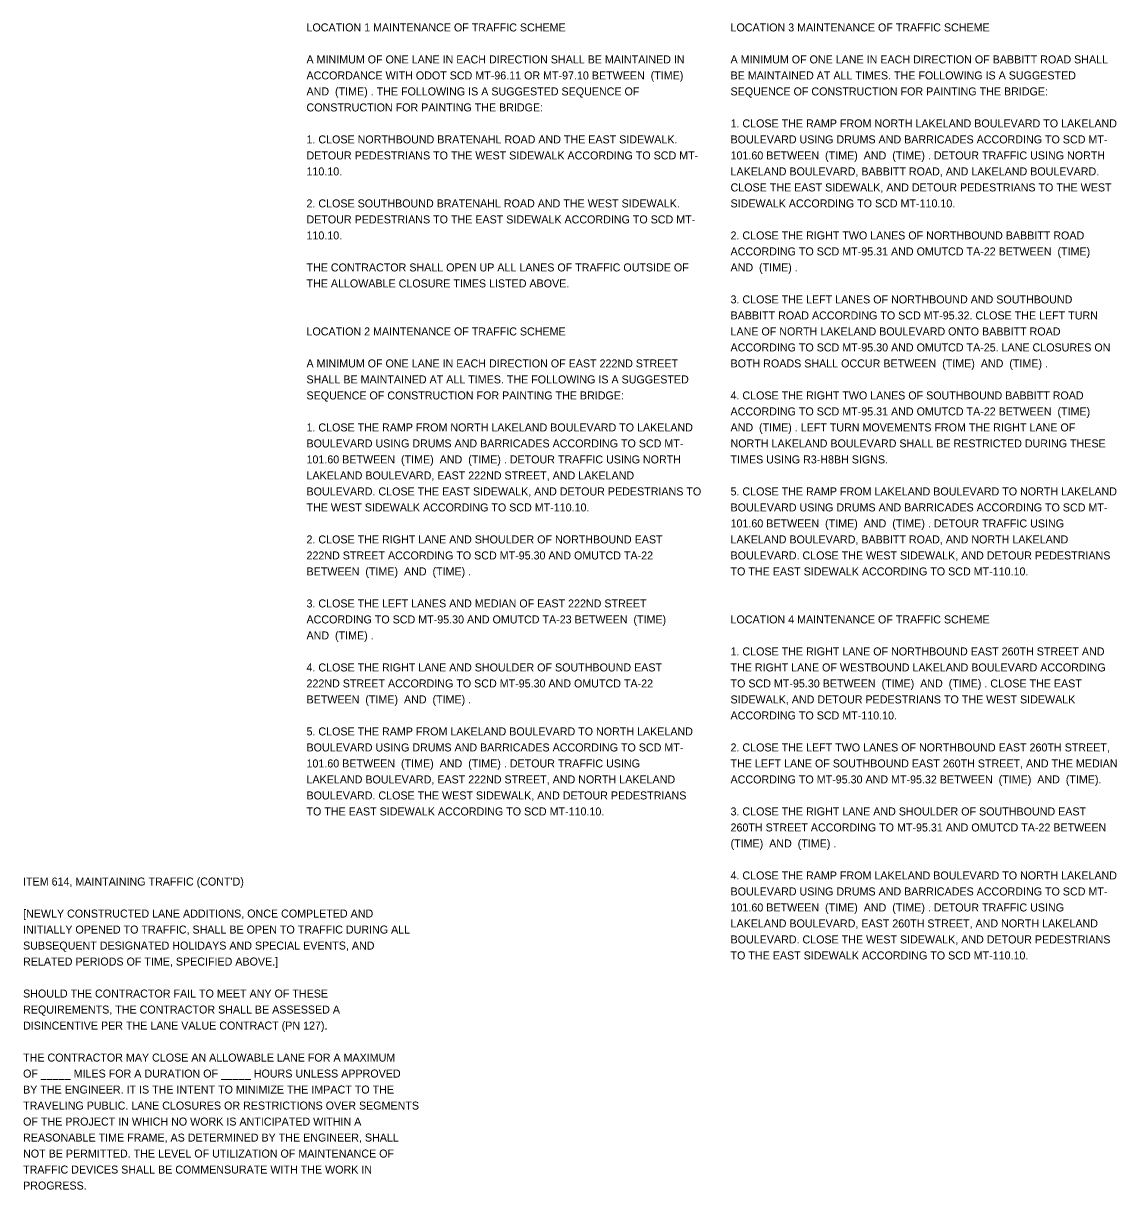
# Model space of a CAD drawing. Extents: x -18.5 to 46, y -14.2 to 42.5.
# Drawn here: x 12.29 to 31.42, y 22.11 to 42.52 of the extents above; entities that cross this region are included whole.
import ezdxf

# ---------------------------------------------------------------- set-up
doc = ezdxf.new("R2010")
doc.units = 0
doc.layers.add('SN_X_Public', color=7, linetype='Continuous')

msp = doc.modelspace()

# ---------------------------------------------------------------- texts
at = {"layer": 'SN_X_Public'}
for s, p in [('LOCATION 1 MAINTENANCE OF TRAFFIC SCHEME ', (17.24, 42.374)), ('LOCATION 3 MAINTENANCE OF TRAFFIC SCHEME ', (24.66, 42.374)), ('A MINIMUM OF ONE LANE IN EACH DIRECTION SHALL BE MAINTAINED IN ', (17.24, 41.814)), ('A MINIMUM OF ONE LANE IN EACH DIRECTION OF BABBITT ROAD SHALL ', (24.66, 41.814)), ('ACCORDANCE WITH ODOT SCD MT-96.11 OR MT-97.10 BETWEEN  (TIME)  ', (17.24, 41.534)), ('BE MAINTAINED AT ALL TIMES. THE FOLLOWING IS A SUGGESTED ', (24.66, 41.534)), ('AND  (TIME) . THE FOLLOWING IS A SUGGESTED SEQUENCE OF ', (17.24, 41.254)), ('SEQUENCE OF CONSTRUCTION FOR PAINTING THE BRIDGE:', (24.66, 41.254)), ('CONSTRUCTION FOR PAINTING THE BRIDGE:', (17.24, 40.974)), ('1. CLOSE THE RAMP FROM NORTH LAKELAND BOULEVARD TO LAKELAND ', (24.66, 40.694)), ('1. CLOSE NORTHBOUND BRATENAHL ROAD AND THE EAST SIDEWALK. ', (17.24, 40.414)), ('BOULEVARD USING DRUMS AND BARRICADES ACCORDING TO SCD MT-', (24.66, 40.414)), ('DETOUR PEDESTRIANS TO THE WEST SIDEWALK ACCORDING TO SCD MT-', (17.24, 40.134)), ('101.60 BETWEEN  (TIME)  AND  (TIME) . DETOUR TRAFFIC USING NORTH ', (24.66, 40.134)), ('110.10.', (17.24, 39.854)), ('LAKELAND BOULEVARD, BABBITT ROAD, AND LAKELAND BOULEVARD. ', (24.66, 39.854)), ('CLOSE THE EAST SIDEWALK, AND DETOUR PEDESTRIANS TO THE WEST ', (24.66, 39.574)), ('2. CLOSE SOUTHBOUND BRATENAHL ROAD AND THE WEST SIDEWALK. ', (17.24, 39.294)), ('SIDEWALK ACCORDING TO SCD MT-110.10.', (24.66, 39.294)), ('DETOUR PEDESTRIANS TO THE EAST SIDEWALK ACCORDING TO SCD MT-', (17.24, 39.014)), ('110.10.', (17.24, 38.734)), ('2. CLOSE THE RIGHT TWO LANES OF NORTHBOUND BABBITT ROAD ', (24.66, 38.734)), ('ACCORDING TO SCD MT-95.31 AND OMUTCD TA-22 BETWEEN  (TIME)  ', (24.66, 38.454)), ('THE CONTRACTOR SHALL OPEN UP ALL LANES OF TRAFFIC OUTSIDE OF ', (17.24, 38.174)), ('AND  (TIME) .', (24.66, 38.174)), ('THE ALLOWABLE CLOSURE TIMES LISTED ABOVE.', (17.24, 37.894)), ('3. CLOSE THE LEFT LANES OF NORTHBOUND AND SOUTHBOUND ', (24.66, 37.614)), ('BABBITT ROAD ACCORDING TO SCD MT-95.32. CLOSE THE LEFT TURN ', (24.66, 37.334)), ('LOCATION 2 MAINTENANCE OF TRAFFIC SCHEME ', (17.24, 37.054)), ('LANE OF NORTH LAKELAND BOULEVARD ONTO BABBITT ROAD ', (24.66, 37.054)), ('ACCORDING TO SCD MT-95.30 AND OMUTCD TA-25. LANE CLOSURES ON ', (24.66, 36.774)), ('A MINIMUM OF ONE LANE IN EACH DIRECTION OF EAST 222ND STREET ', (17.24, 36.494)), ('BOTH ROADS SHALL OCCUR BETWEEN  (TIME)  AND  (TIME) .', (24.66, 36.494)), ('SHALL BE MAINTAINED AT ALL TIMES. THE FOLLOWING IS A SUGGESTED ', (17.24, 36.214)), ('SEQUENCE OF CONSTRUCTION FOR PAINTING THE BRIDGE:', (17.24, 35.934)), ('4. CLOSE THE RIGHT TWO LANES OF SOUTHBOUND BABBITT ROAD ', (24.66, 35.934)), ('ACCORDING TO SCD MT-95.31 AND OMUTCD TA-22 BETWEEN  (TIME)  ', (24.66, 35.654)), ('1. CLOSE THE RAMP FROM NORTH LAKELAND BOULEVARD TO LAKELAND ', (17.24, 35.374)), ('AND  (TIME) . LEFT TURN MOVEMENTS FROM THE RIGHT LANE OF ', (24.66, 35.374)), ('BOULEVARD USING DRUMS AND BARRICADES ACCORDING TO SCD MT-', (17.24, 35.094)), ('NORTH LAKELAND BOULEVARD SHALL BE RESTRICTED DURING THESE ', (24.66, 35.094)), ('101.60 BETWEEN  (TIME)  AND  (TIME) . DETOUR TRAFFIC USING NORTH ', (17.24, 34.814)), ('TIMES USING R3-H8BH SIGNS.', (24.66, 34.814)), ('LAKELAND BOULEVARD, EAST 222ND STREET, AND LAKELAND ', (17.24, 34.534)), ('BOULEVARD. CLOSE THE EAST SIDEWALK, AND DETOUR PEDESTRIANS TO ', (17.24, 34.254)), ('5. CLOSE THE RAMP FROM LAKELAND BOULEVARD TO NORTH LAKELAND ', (24.66, 34.254)), ('THE WEST SIDEWALK ACCORDING TO SCD MT-110.10.', (17.24, 33.974)), ('BOULEVARD USING DRUMS AND BARRICADES ACCORDING TO SCD MT-', (24.66, 33.974)), ('101.60 BETWEEN  (TIME)  AND  (TIME) . DETOUR TRAFFIC USING ', (24.66, 33.694)), ('2. CLOSE THE RIGHT LANE AND SHOULDER OF NORTHBOUND EAST ', (17.24, 33.414)), ('LAKELAND BOULEVARD, BABBITT ROAD, AND NORTH LAKELAND ', (24.66, 33.414)), ('222ND STREET ACCORDING TO SCD MT-95.30 AND OMUTCD TA-22 ', (17.24, 33.134)), ('BOULEVARD. CLOSE THE WEST SIDEWALK, AND DETOUR PEDESTRIANS ', (24.66, 33.134)), ('BETWEEN  (TIME)  AND  (TIME) .', (17.24, 32.854)), ('TO THE EAST SIDEWALK ACCORDING TO SCD MT-110.10.', (24.66, 32.854)), ('3. CLOSE THE LEFT LANES AND MEDIAN OF EAST 222ND STREET ', (17.24, 32.294)), ('ACCORDING TO SCD MT-95.30 AND OMUTCD TA-23 BETWEEN  (TIME)  ', (17.24, 32.014)), ('LOCATION 4 MAINTENANCE OF TRAFFIC SCHEME ', (24.66, 32.014)), ('AND  (TIME) .', (17.24, 31.734)), ('1. CLOSE THE RIGHT LANE OF NORTHBOUND EAST 260TH STREET AND ', (24.66, 31.454)), ('4. CLOSE THE RIGHT LANE AND SHOULDER OF SOUTHBOUND EAST ', (17.24, 31.174)), ('THE RIGHT LANE OF WESTBOUND LAKELAND BOULEVARD ACCORDING ', (24.66, 31.174)), ('222ND STREET ACCORDING TO SCD MT-95.30 AND OMUTCD TA-22 ', (17.24, 30.894)), ('TO SCD MT-95.30 BETWEEN  (TIME)  AND  (TIME) . CLOSE THE EAST ', (24.66, 30.894)), ('BETWEEN  (TIME)  AND  (TIME) .', (17.24, 30.614)), ('SIDEWALK, AND DETOUR PEDESTRIANS TO THE WEST SIDEWALK ', (24.66, 30.614)), ('ACCORDING TO SCD MT-110.10.', (24.66, 30.334)), ('5. CLOSE THE RAMP FROM LAKELAND BOULEVARD TO NORTH LAKELAND ', (17.24, 30.054)), ('BOULEVARD USING DRUMS AND BARRICADES ACCORDING TO SCD MT-', (17.24, 29.774)), ('2. CLOSE THE LEFT TWO LANES OF NORTHBOUND EAST 260TH STREET, ', (24.66, 29.774)), ('101.60 BETWEEN  (TIME)  AND  (TIME) . DETOUR TRAFFIC USING ', (17.24, 29.494)), ('THE LEFT LANE OF SOUTHBOUND EAST 260TH STREET, AND THE MEDIAN ', (24.66, 29.494)), ('LAKELAND BOULEVARD, EAST 222ND STREET, AND NORTH LAKELAND ', (17.24, 29.214)), ('ACCORDING TO MT-95.30 AND MT-95.32 BETWEEN  (TIME)  AND  (TIME).', (24.66, 29.214)), ('BOULEVARD. CLOSE THE WEST SIDEWALK, AND DETOUR PEDESTRIANS ', (17.24, 28.934)), ('TO THE EAST SIDEWALK ACCORDING TO SCD MT-110.10.', (17.24, 28.654)), ('3. CLOSE THE RIGHT LANE AND SHOULDER OF SOUTHBOUND EAST ', (24.66, 28.654)), ('260TH STREET ACCORDING TO MT-95.31 AND OMUTCD TA-22 BETWEEN  ', (24.66, 28.374)), ('(TIME)  AND  (TIME) .', (24.66, 28.094)), ("ITEM 614, MAINTAINING TRAFFIC (CONT'D)", (12.281, 27.427)), ('4. CLOSE THE RAMP FROM LAKELAND BOULEVARD TO NORTH LAKELAND ', (24.66, 27.534)), ('BOULEVARD USING DRUMS AND BARRICADES ACCORDING TO SCD MT-', (24.66, 27.254)), ('[NEWLY CONSTRUCTED LANE ADDITIONS, ONCE COMPLETED AND ', (12.281, 26.867)), ('101.60 BETWEEN  (TIME)  AND  (TIME) . DETOUR TRAFFIC USING ', (24.66, 26.974)), ('LAKELAND BOULEVARD, EAST 260TH STREET, AND NORTH LAKELAND ', (24.66, 26.694)), ('INITIALLY OPENED TO TRAFFIC, SHALL BE OPEN TO TRAFFIC DURING ALL ', (12.281, 26.587)), ('BOULEVARD. CLOSE THE WEST SIDEWALK, AND DETOUR PEDESTRIANS ', (24.66, 26.414)), ('SUBSEQUENT DESIGNATED HOLIDAYS AND SPECIAL EVENTS, AND', (12.281, 26.307)), ('RELATED PERIODS OF TIME, SPECIFIED ABOVE.]', (12.281, 26.027)), ('TO THE EAST SIDEWALK ACCORDING TO SCD MT-110.10.', (24.66, 26.134)), ('SHOULD THE CONTRACTOR FAIL TO MEET ANY OF THESE ', (12.281, 25.467)), ('REQUIREMENTS, THE CONTRACTOR SHALL BE ASSESSED A ', (12.281, 25.187)), ('DISINCENTIVE PER THE LANE VALUE CONTRACT (PN 127).', (12.281, 24.907)), ('THE CONTRACTOR MAY CLOSE AN ALLOWABLE LANE FOR A MAXIMUM ', (12.281, 24.347)), ('OF _____ MILES FOR A DURATION OF _____ HOURS UNLESS APPROVED ', (12.281, 24.067)), ('BY THE ENGINEER. IT IS THE INTENT TO MINIMIZE THE IMPACT TO THE ', (12.281, 23.787)), ('TRAVELING PUBLIC. LANE CLOSURES OR RESTRICTIONS OVER SEGMENTS ', (12.281, 23.507)), ('OF THE PROJECT IN WHICH NO WORK IS ANTICIPATED WITHIN A ', (12.281, 23.227)), ('REASONABLE TIME FRAME, AS DETERMINED BY THE ENGINEER, SHALL ', (12.281, 22.947)), ('NOT BE PERMITTED. THE LEVEL OF UTILIZATION OF MAINTENANCE OF ', (12.281, 22.667)), ('TRAFFIC DEVICES SHALL BE COMMENSURATE WITH THE WORK IN ', (12.281, 22.387)), ('PROGRESS.', (12.281, 22.107))]:
    msp.add_text(s, height=0.14, dxfattribs=at).set_placement(p)

doc.saveas('drawing.dxf')
